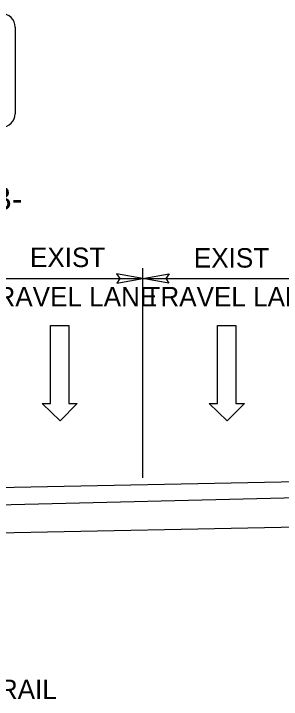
# Model space of a CAD drawing. Extents: x 1726582 to 1728895, y 538986 to 541550.
# Drawn here: x 1727240.4 to 1727336.6, y 539541.5 to 539788.1 of the extents above; entities that cross this region are included whole.
import ezdxf

# ---------------------------------------------------------------- set-up
doc = ezdxf.new("R2010")
doc.units = 0
for name, color, linetype in [('Default', 7, 'Continuous'), ('GSProposed', 7, 'Continuous'), ('GSRemove', 7, 'Continuous'), ('GSReplace', 7, 'Continuous'), ('Old_Level_2', 7, 'Continuous')]:
    doc.layers.add(name, color=color, linetype=linetype)

msp = doc.modelspace()

# ---------------------------------------------------------------- linework, layer by layer
at = {"layer": 'Default'}
for p, q in [((1727286.83, 539621.12), (1727286.83, 539696.51)), ((1727226.89, 539692.81), (1727286.94, 539692.81)), ((1727286.94, 539692.81), (1727346.99, 539692.81)), ((1727253.68, 539647.91), (1727253.68, 539675.91)), ((1727253.68, 539675.91), (1727260.28, 539675.91)), ((1727260.28, 539675.91), (1727260.28, 539647.91)), ((1727313.73, 539647.91), (1727313.73, 539675.91)), ((1727313.73, 539675.91), (1727320.33, 539675.91)), ((1727320.33, 539675.91), (1727320.33, 539647.91)), ((1727257.08, 539641.61), (1727250.68, 539647.91)), ((1727250.68, 539647.91), (1727253.68, 539647.91)), ((1727263.28, 539647.91), (1727257.08, 539641.61)), ((1727260.28, 539647.91), (1727263.28, 539647.91)), ((1727317.13, 539641.61), (1727310.73, 539647.91)), ((1727310.73, 539647.91), (1727313.73, 539647.91)), ((1727323.33, 539647.91), (1727317.13, 539641.61)), ((1727320.33, 539647.91), (1727323.33, 539647.91))]:
    msp.add_line(p, q, dxfattribs=at)
for points in [[(1727277.46, 539691.19), (1727286.83, 539692.81), (1727277.4, 539694.47), (1727278.6, 539692.81)], [(1727296.21, 539691.19), (1727286.83, 539692.81), (1727296.26, 539694.47), (1727295.07, 539692.81)]]:
    msp.add_lwpolyline(points, close=True, dxfattribs=at)
at = {"layer": 'GSReplace'}
for p, q in [((1727226.79, 539617.45), (1727461.04, 539622.13)), ((1727226.79, 539611.2), (1727461.04, 539617.02)), ((1727226.79, 539601.19), (1727461.04, 539605.87))]:
    msp.add_line(p, q, dxfattribs=at)
at = {"layer": 'Old_Level_2'}
msp.add_line((1727240.92, 539783.26), (1727240.92, 539752.06), dxfattribs=at)
for centre, start, end in [((1727236.12, 539783.26), 0, 90), ((1727236.12, 539752.06), 270, 0)]:
    msp.add_arc(centre, 4.8, start, end, dxfattribs=at)

# ---------------------------------------------------------------- texts
at = {"layer": 'Default'}
msp.add_text('EXISTING GUARDRAIL', height=7, dxfattribs=at).set_placement((1727155.01, 539541.58))
at = {"layer": 'GSProposed'}
for s, height, p in [('EXIST', 7.005, (1727246.28, 539696.93)), ('EXIST', 7.005, (1727305.19, 539696.74)), ('TRAVEL LANE', 7.0055, (1727228.52, 539682.8)), ('TRAVEL LANE', 7.0055, (1727287.43, 539682.8))]:
    msp.add_text(s, height=height, dxfattribs=at).set_placement(p)
at = {"layer": 'GSRemove'}
msp.add_text('-L_WB-', height=8.421, dxfattribs=at).set_placement((1727205.36, 539717.37))

doc.saveas('drawing.dxf')
